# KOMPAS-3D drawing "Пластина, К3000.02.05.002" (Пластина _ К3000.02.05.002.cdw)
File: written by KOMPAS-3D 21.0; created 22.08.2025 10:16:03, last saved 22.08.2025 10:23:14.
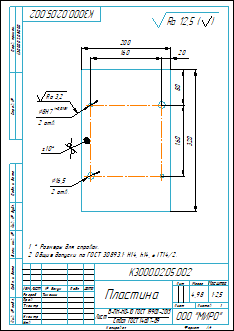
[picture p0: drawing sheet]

Sheet 1: A4, portrait

Document properties: Автор: Lutik; Знак неуказанной шероховатости: 4; Параметр неуказанной шероховатости: Ra 12,5; Масса: 4.982538

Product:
- Part/product: Пластина  | designation К3000.02.05.002
    Материал: Лист$dБ-ПН-НО-10 ГОСТ 19903-2015;Ст3сп ГОСТ 14637-89$ (density 7850 kg/m3)
    Масса: 4.982538
    Форматы листов документа: A4

Title block, sheet 1: Наименование: Пластина; designation: К3000.02.05.002; Материал: Лист Б-ПН-НО-10 ГОСТ 19903-2015 Ст3сп ГОСТ 14637-89; Масса: 4,98; Количество листов документа: 1; organisation: ООО "МИРО"; Форматы листов документа: A4; stored path: C:\Users\Lutik\YandexDisk\Документы\Новая папка\Бабка задняя\2D\Кронштейн_К3000.02.05.000\Пластина _ К3000.02.05.002.cdw; Разработал: Тимонин

Views: Вид 1, Слева
Referenced files in C:\Users\Lutik\YandexDisk\Документы\Новая папка\Бабка задняя\3D\: Пластина_42.m3d
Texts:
  Ra 3,2
  Ra 12,5
  Ra 12,5 ( )
  К3000.02.05.002 Пластина
Dimensions and other numbers on the sheet: 200; 320; 20; 160; 80; 16,5; 2 отв.; 8; 1:2,5; 1; 4,98

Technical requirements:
  * Размеры для справок.
  Общие допуски по ГОСТ 30893.1: Н14, h14, ± IT14/2.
